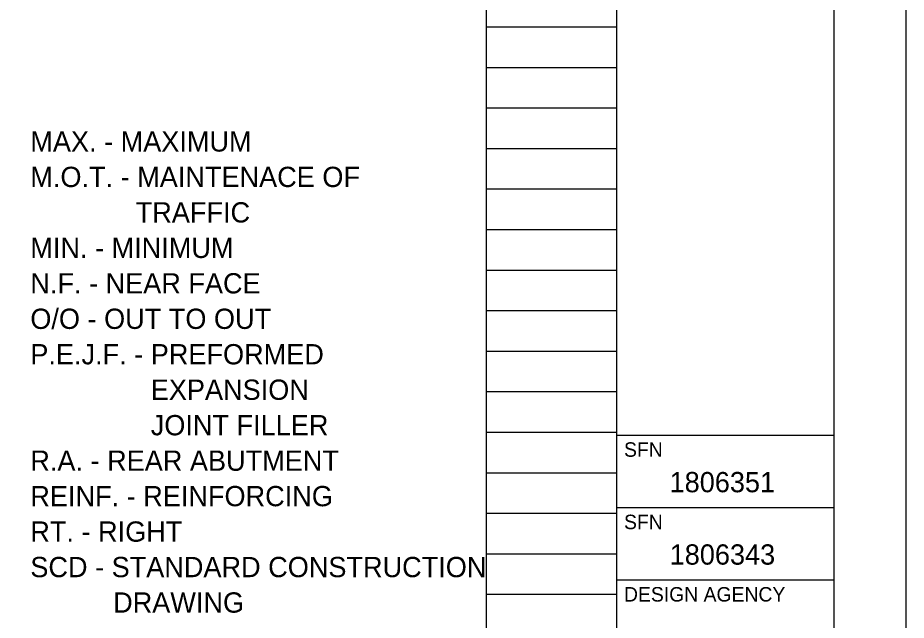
# Model space of a CAD drawing. Extents: x 0 to 34, y 0 to 22.
# Drawn here: x 27.86 to 34, y 4.72 to 8.88 of the extents above; entities that cross this region are included whole.
import ezdxf

# ---------------------------------------------------------------- set-up
doc = ezdxf.new("R2010")
doc.units = 0
for name, color, linetype in [('SH_Border', 7, 'Continuous'), ('SH_Cut_Line', 7, 'Continuous'), ('SH_Data', 7, 'Continuous'), ('SH_Text', 7, 'Continuous')]:
    doc.layers.add(name, color=color, linetype=linetype)

msp = doc.modelspace()

# ---------------------------------------------------------------- linework, layer by layer
at = {"layer": 'SH_Border'}
for p, q in [((32, 0.5), (32, 21.5)), ((32, 6), (33.5, 6)), ((32, 5.5), (33.5, 5.5)), ((32, 5), (33.5, 5))]:
    msp.add_line(p, q, dxfattribs=at)
msp.add_lwpolyline([(1.5, 21.5), (33.5, 21.5), (33.5, 0.5), (1.5, 0.5)], close=True, dxfattribs=at)
at = {"layer": 'SH_Cut_Line'}
msp.add_lwpolyline([(0, 0), (34, 0), (34, 22), (0, 22)], close=True, dxfattribs=at)
at = {"layer": 'SH_Data'}
for p, q in [((31.1, 0.98), (31.1, 21.14)), ((32, 0.98), (32, 21.14)), ((31.1, 8.82), (32, 8.82)), ((31.1, 8.54), (32, 8.54)), ((31.1, 8.26), (32, 8.26)), ((31.1, 7.98), (32, 7.98)), ((31.1, 7.7), (32, 7.7)), ((31.1, 7.42), (32, 7.42)), ((31.1, 7.14), (32, 7.14)), ((31.1, 6.86), (32, 6.86)), ((31.1, 6.58), (32, 6.58)), ((31.1, 6.3), (32, 6.3)), ((31.1, 6.02), (32, 6.02)), ((31.1, 5.74), (32, 5.74)), ((32.75, 5.675), (32.75, 5.675)), ((31.1, 5.46), (32, 5.46)), ((31.1, 5.18), (32, 5.18)), ((32.75, 5.175), (32.75, 5.175)), ((31.1, 4.9), (32, 4.9))]:
    msp.add_line(p, q, dxfattribs=at)

# ---------------------------------------------------------------- texts
for s, height, p in [('SFN', 0.1, (32.05, 5.85)), ('1806351', 0.14, (32.3649, 5.605)), ('SFN', 0.1, (32.05, 5.35)), ('1806343', 0.14, (32.3656, 5.105)), ('DESIGN AGENCY', 0.1, (32.05, 4.85))]:
    msp.add_text(s, height=height, dxfattribs=at).set_placement(p)
at = {"layer": 'SH_Text'}
for s, p in [('MAX. - MAXIMUM', (27.9478, 7.9584)), ('M.O.T. - MAINTENACE OF ', (27.9478, 7.7134)), ('              TRAFFIC', (27.9478, 7.4684)), ('MIN. - MINIMUM', (27.9478, 7.2234)), ('N.F. - NEAR FACE', (27.9478, 6.9784)), ('O/O - OUT TO OUT', (27.9478, 6.7334)), ('P.E.J.F. - PREFORMED ', (27.9478, 6.4884)), ('                EXPANSION ', (27.9478, 6.2434)), ('                JOINT FILLER', (27.9478, 5.9984)), ('R.A. - REAR ABUTMENT', (27.9478, 5.7534)), ('REINF. - REINFORCING', (27.9478, 5.5084)), ('RT. - RIGHT', (27.9478, 5.2634)), ('SCD - STANDARD CONSTRUCTION', (27.9478, 5.0184)), ('           DRAWING', (27.9478, 4.7734))]:
    msp.add_text(s, height=0.14, dxfattribs=at).set_placement(p)

doc.saveas('drawing.dxf')
